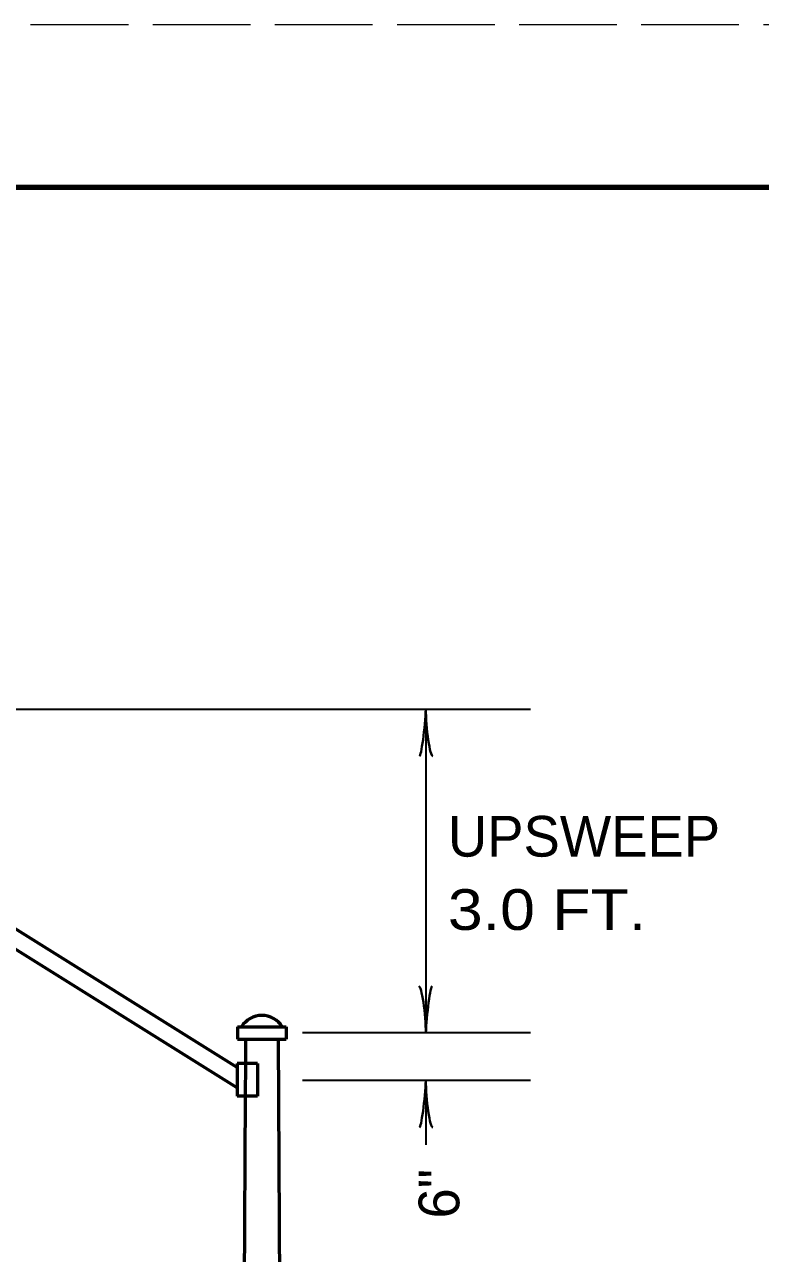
# Model space of a CAD drawing. Extents: x 6488 to 7168, y 276 to 716.
# Drawn here: x 6599.8 to 6645, y 640.6 to 716 of the extents above; entities that cross this region are included whole.
import ezdxf

# ---------------------------------------------------------------- set-up
doc = ezdxf.new("R2010")
doc.units = 0
doc.linetypes.add('LONG_DASHED', pattern=[7.5, 6, -1.5])
doc.layers.add('1', color=7, linetype='Continuous', lineweight=35)
doc.layers.add('61', color=7, linetype='Continuous', lineweight=35)

msp = doc.modelspace()

# ---------------------------------------------------------------- linework, layer by layer
at = {"layer": '1'}
for p, q in [((6573.467, 674.006), (6630.842, 674.006)), ((6624.41, 674.006), (6624.41, 654.131)), ((6630.842, 654.131), (6616.842, 654.131)), ((6630.842, 651.207), (6616.842, 651.207)), ((6624.41, 651.207), (6624.41, 647.256))]:
    msp.add_line(p, q, dxfattribs=at)
at = {"layer": '1', "lineweight": 53}
for p, q in [((6612.832, 652.006), (6583.998, 670.023)), ((6612.825, 650.756), (6583.143, 669.303)), ((6612.842, 654.506), (6615.842, 654.506)), ((6612.842, 654.506), (6612.842, 653.756)), ((6615.842, 654.506), (6615.842, 653.756)), ((6612.842, 653.756), (6615.842, 653.756)), ((6615.342, 653.756), (6616.092, 525.256)), ((6612.833, 652.256), (6612.822, 650.256)), ((6614.083, 652.256), (6612.833, 652.256)), ((6614.083, 652.256), (6614.072, 650.256)), ((6613.322, 650.256), (6612.592, 525.256)), ((6614.083, 650.256), (6612.822, 650.256))]:
    msp.add_line(p, q, dxfattribs=at)
msp.add_lwpolyline([(6613.342, 653.756), (6613.333, 652.256), (6613.322, 650.256)], dxfattribs=at)
msp.add_arc((6614.342, 653.748), 1.462, 31.24858, 148.75141, dxfattribs=at)
at = {"layer": '1', "lineweight": 40}
for centre, major_axis, ratio, start_param, end_param in [((6624.199, 672.885), (0.176, 1.756), 0.07063, 3.140715, 5.41811), ((6624.687, 672.915), (-0.156, 1.786), 0.122415, 0.896353, 3.141593), ((6624.134, 655.222), (0.156, -1.786), 0.122415, 0.896353, 3.141593), ((6624.622, 655.252), (-0.176, -1.756), 0.07063, 3.140715, 5.41811), ((6624.199, 650.087), (0.176, 1.756), 0.07063, 3.140715, 5.41811), ((6624.687, 650.116), (-0.156, 1.786), 0.122415, 0.896353, 3.141593)]:
    msp.add_ellipse(centre, major_axis=major_axis, ratio=ratio, start_param=start_param, end_param=end_param, dxfattribs=at)
at = {"layer": '61', "linetype": 'LONG_DASHED', "lineweight": 13}
msp.add_line((6487.643, 716.04), (7167.663, 716.04), dxfattribs=at)
at = {"layer": '61', "lineweight": 158}
msp.add_lwpolyline([(7156.683, 706.04), (6517.643, 706.04), (6517.643, 286.02)], dxfattribs=at)

# ---------------------------------------------------------------- texts
at = {"layer": '1'}
msp.add_text('UPSWEEP', height=2.5, dxfattribs=at).set_placement((6625.767, 664.957))
at = {"layer": '1', "width": 1.15}
msp.add_text('3.0 FT.', height=2.5, dxfattribs=at).set_placement((6625.767, 660.457))
at = {"layer": '1'}
msp.add_text('6"', height=2.5, rotation=90, dxfattribs=at).set_placement((6626.47, 642.736))

doc.saveas('drawing.dxf')
